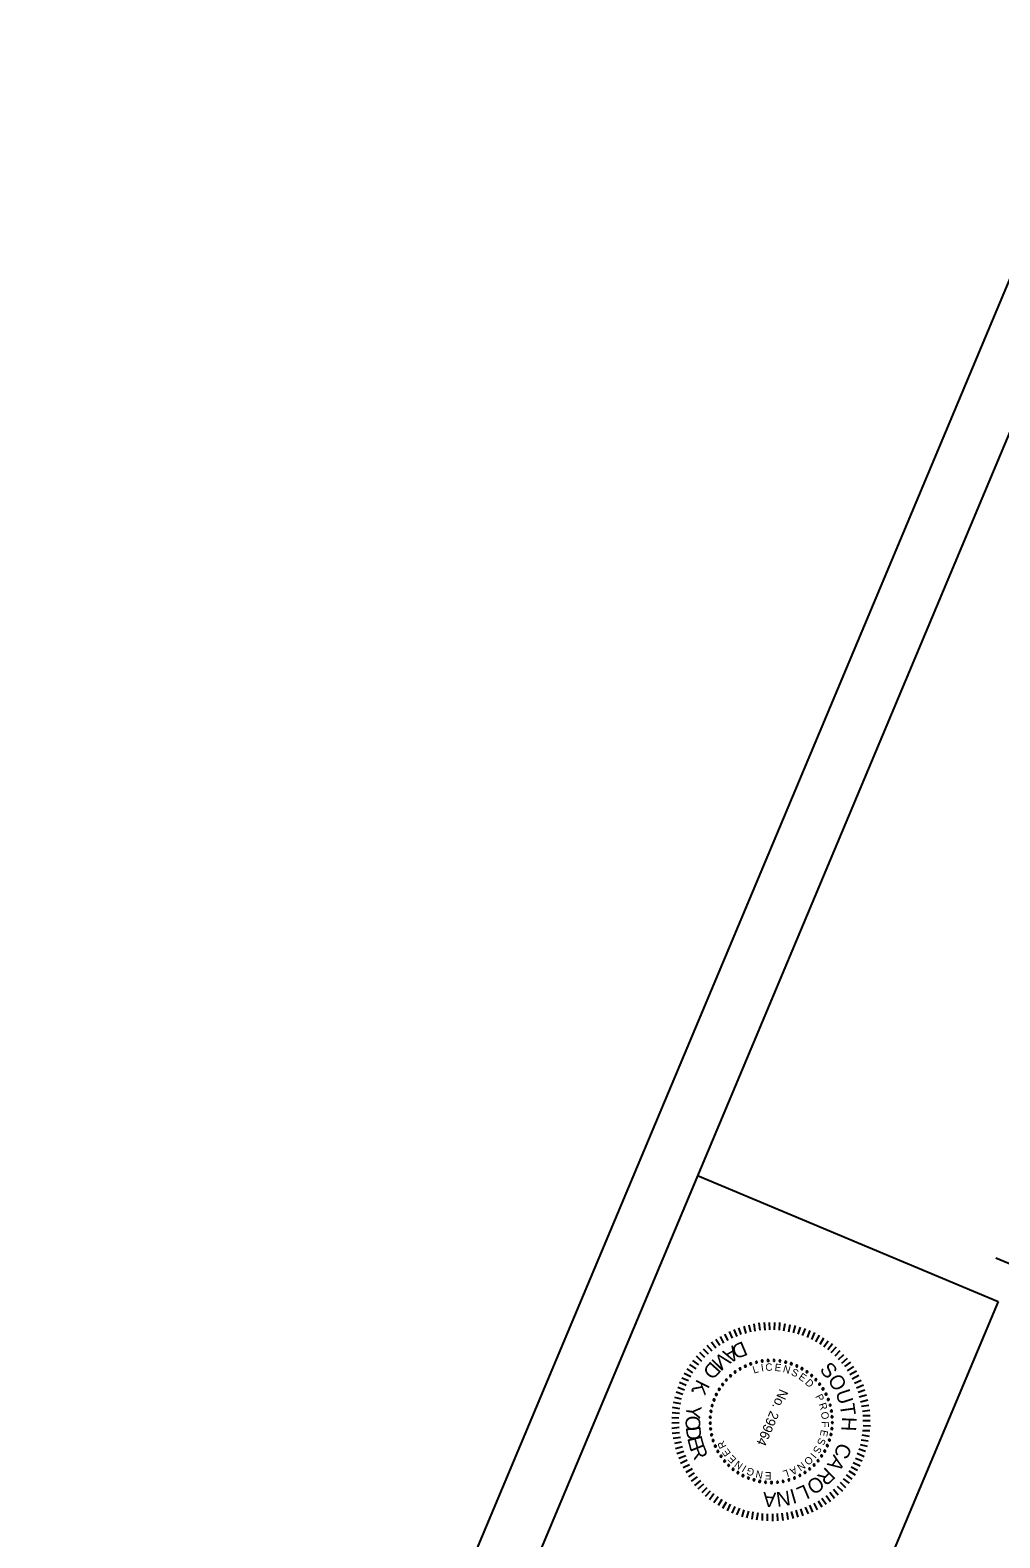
# Model space of a CAD drawing. Extents: x 1968564 to 1968701, y 796599 to 796766.
# Drawn here: x 1968563.8 to 1968596.6, y 796669.3 to 796720.2 of the extents above; entities that cross this region are included whole.
import ezdxf

# ---------------------------------------------------------------- set-up
doc = ezdxf.new("R2010")
doc.units = 0
for name, color, linetype in [('BR_AUTO DIMENSION', 7, 'Continuous'), ('BR_BORDER LINES', 7, 'Continuous'), ('BR_TEXT', 7, 'Continuous'), ('Level 31', 7, 'Continuous')]:
    doc.layers.add(name, color=color, linetype=linetype)

msp = doc.modelspace()

# ---------------------------------------------------------------- linework, layer by layer
at = {"layer": 'BR_AUTO DIMENSION'}
msp.add_line((1968596.437, 796678.704), (1968603.817, 796675.609), dxfattribs=at)
at = {"layer": 'BR_BORDER LINES'}
for p, q in [((1968618.549, 796758.212), (1968566.464, 796634.028)), ((1968586.369, 796681.485), (1968596.513, 796677.23)), ((1968596.513, 796677.23), (1968588.212, 796657.44))]:
    msp.add_line(p, q, dxfattribs=at)
at = {"layer": 'BR_TEXT'}
for p, q in [((1968587.703, 796676.052), (1968587.606, 796676.288)), ((1968587.843, 796676.119), (1968587.761, 796676.345)), ((1968588.006, 796676.158), (1968587.939, 796676.403)), ((1968588.169, 796676.199), (1968588.112, 796676.441)), ((1968588.31, 796676.232), (1968588.279, 796676.481)), ((1968588.484, 796676.263), (1968588.452, 796676.511)), ((1968588.647, 796676.267), (1968588.626, 796676.523)), ((1968588.806, 796676.274), (1968588.796, 796676.528)), ((1968588.969, 796676.278), (1968588.982, 796676.527)), ((1968589.13, 796676.262), (1968589.148, 796676.523)), ((1968589.284, 796676.248), (1968589.327, 796676.495)), ((1968589.45, 796676.207), (1968589.498, 796676.458)), ((1968589.611, 796676.182), (1968589.673, 796676.421)), ((1968589.769, 796676.133), (1968589.838, 796676.372)), ((1968589.915, 796676.081), (1968590.011, 796676.321)), ((1968590.076, 796676.02), (1968590.175, 796676.25)), ((1968586.861, 796675.562), (1968586.698, 796675.748)), ((1968586.988, 796675.657), (1968586.838, 796675.856)), ((1968587.125, 796675.751), (1968586.982, 796675.947)), ((1968587.253, 796675.831), (1968587.138, 796676.052)), ((1968587.4, 796675.913), (1968587.29, 796676.136)), ((1968587.546, 796675.993), (1968587.442, 796676.22)), ((1968590.224, 796675.949), (1968590.326, 796676.185)), ((1968590.366, 796675.877), (1968590.488, 796676.093)), ((1968590.51, 796675.796), (1968590.635, 796676.008)), ((1968590.626, 796675.702), (1968590.782, 796675.907)), ((1968590.77, 796675.61), (1968590.92, 796675.811)), ((1968586.408, 796675.099), (1968586.212, 796675.243)), ((1968586.509, 796675.212), (1968586.33, 796675.386)), ((1968586.616, 796675.339), (1968586.441, 796675.507)), ((1968586.74, 796675.453), (1968586.572, 796675.63)), ((1968590.884, 796675.509), (1968591.063, 796675.701)), ((1968591.013, 796675.401), (1968591.184, 796675.582)), ((1968591.128, 796675.277), (1968591.31, 796675.449)), ((1968591.236, 796675.156), (1968591.427, 796675.321)), ((1968586.137, 796674.692), (1968585.916, 796674.806)), ((1968586.215, 796674.831), (1968586.015, 796674.957)), ((1968586.318, 796674.958), (1968586.114, 796675.109)), ((1968591.335, 796675.039), (1968591.537, 796675.187)), ((1968591.433, 796674.892), (1968591.638, 796675.039)), ((1968591.507, 796674.767), (1968591.73, 796674.888)), ((1968591.589, 796674.62), (1968591.809, 796674.742)), ((1968585.932, 796674.242), (1968585.702, 796674.333)), ((1968585.989, 796674.401), (1968585.765, 796674.497)), ((1968586.065, 796674.551), (1968585.838, 796674.649)), ((1968591.666, 796674.478), (1968591.89, 796674.573)), ((1968591.734, 796674.322), (1968591.965, 796674.417)), ((1968591.789, 796674.172), (1968592.019, 796674.256)), ((1968585.81, 796673.775), (1968585.561, 796673.822)), ((1968585.833, 796673.941), (1968585.602, 796673.995)), ((1968585.878, 796674.09), (1968585.644, 796674.172)), ((1968591.829, 796674.012), (1968592.076, 796674.082)), ((1968591.871, 796673.849), (1968592.119, 796673.914)), ((1968591.901, 796673.701), (1968592.148, 796673.73)), ((1968585.738, 796673.294), (1968585.496, 796673.305)), ((1968585.757, 796673.458), (1968585.508, 796673.472)), ((1968585.771, 796673.613), (1968585.529, 796673.65)), ((1968591.934, 796673.534), (1968592.181, 796673.562)), ((1968591.946, 796673.38), (1968592.193, 796673.39)), ((1968591.951, 796673.217), (1968592.194, 796673.217)), ((1968585.745, 796673.135), (1968585.496, 796673.122)), ((1968585.751, 796672.975), (1968585.497, 796672.95)), ((1968585.764, 796672.805), (1968585.515, 796672.774)), ((1968591.919, 796672.734), (1968592.164, 796672.688)), ((1968591.938, 796672.882), (1968592.184, 796672.874)), ((1968591.953, 796673.048), (1968592.201, 796673.035)), ((1968585.793, 796672.647), (1968585.548, 796672.607)), ((1968585.819, 796672.49), (1968585.586, 796672.434)), ((1968585.862, 796672.33), (1968585.625, 796672.256)), ((1968585.907, 796672.172), (1968585.669, 796672.088)), ((1968591.811, 796672.257), (1968592.042, 796672.177)), ((1968591.858, 796672.409), (1968592.097, 796672.347)), ((1968591.892, 796672.566), (1968592.132, 796672.526)), ((1968585.973, 796672.021), (1968585.738, 796671.935)), ((1968586.023, 796671.876), (1968585.797, 796671.768)), ((1968586.102, 796671.723), (1968585.884, 796671.615)), ((1968591.553, 796671.655), (1968591.77, 796671.543)), ((1968591.626, 796671.799), (1968591.86, 796671.691)), ((1968591.702, 796671.949), (1968591.929, 796671.852)), ((1968591.759, 796672.108), (1968591.995, 796672.006)), ((1968586.187, 796671.581), (1968585.975, 796671.46)), ((1968586.259, 796671.453), (1968586.06, 796671.311)), ((1968586.36, 796671.313), (1968586.159, 796671.168)), ((1968586.467, 796671.189), (1968586.266, 796671.025)), ((1968591.281, 796671.248), (1968591.481, 796671.095)), ((1968591.384, 796671.383), (1968591.58, 796671.239)), ((1968591.476, 796671.519), (1968591.684, 796671.385)), ((1968586.571, 796671.066), (1968586.381, 796670.901)), ((1968586.68, 796670.944), (1968586.511, 796670.77)), ((1968586.8, 796670.833), (1968586.63, 796670.655)), ((1968586.919, 796670.737), (1968586.771, 796670.539)), ((1968587.06, 796670.639), (1968586.915, 796670.44)), ((1968590.71, 796670.683), (1968590.859, 796670.481)), ((1968590.836, 796670.793), (1968590.992, 796670.592)), ((1968590.956, 796670.898), (1968591.117, 796670.71)), ((1968591.076, 796671.004), (1968591.256, 796670.833)), ((1968591.185, 796671.129), (1968591.363, 796670.959)), ((1968587.192, 796670.545), (1968587.064, 796670.342)), ((1968587.333, 796670.455), (1968587.208, 796670.243)), ((1968587.472, 796670.388), (1968587.371, 796670.17)), ((1968587.626, 796670.311), (1968587.529, 796670.087)), ((1968587.781, 796670.255), (1968587.686, 796670.034)), ((1968587.929, 796670.199), (1968587.858, 796669.964)), ((1968588.091, 796670.159), (1968588.026, 796669.93)), ((1968588.237, 796670.134), (1968588.199, 796669.889)), ((1968589.525, 796670.149), (1968589.593, 796669.907)), ((1968589.686, 796670.185), (1968589.755, 796669.953)), ((1968589.846, 796670.236), (1968589.926, 796669.996)), ((1968590.004, 796670.291), (1968590.097, 796670.064)), ((1968590.15, 796670.352), (1968590.246, 796670.124)), ((1968590.291, 796670.429), (1968590.411, 796670.202)), ((1968590.437, 796670.508), (1968590.566, 796670.296)), ((1968590.569, 796670.598), (1968590.715, 796670.389)), ((1968588.405, 796670.099), (1968588.364, 796669.855)), ((1968588.554, 796670.08), (1968588.545, 796669.834)), ((1968588.724, 796670.067), (1968588.713, 796669.825)), ((1968588.893, 796670.069), (1968588.895, 796669.822)), ((1968589.057, 796670.077), (1968589.067, 796669.823)), ((1968589.211, 796670.089), (1968589.244, 796669.844)), ((1968589.382, 796670.113), (1968589.42, 796669.869))]:
    msp.add_line(p, q, dxfattribs=at)
for centre, start, end in [((1968588.355, 796675.186), 14.1575, 194.1575), ((1968588.55, 796675.225), 8.619, 188.619), ((1968588.55, 796675.225), 188.619, 8.619), ((1968588.749, 796675.244), 3.0805, 183.0805), ((1968588.749, 796675.244), 183.0805, 3.0805), ((1968588.948, 796675.245), 357.5421, 177.5421), ((1968588.948, 796675.245), 177.5421, 357.5421), ((1968589.147, 796675.227), 352.0036, 172.0036), ((1968589.147, 796675.227), 172.0036, 352.0036), ((1968589.342, 796675.189), 346.4652, 166.4652), ((1968587.482, 796674.724), 41.8498, 221.8498), ((1968587.482, 796674.724), 221.8498, 41.8498), ((1968587.637, 796674.849), 36.3113, 216.3113), ((1968587.637, 796674.849), 216.3113, 36.3113), ((1968587.804, 796674.959), 30.7728, 210.7728), ((1968587.804, 796674.959), 210.7728, 30.7728), ((1968587.98, 796675.052), 25.2344, 205.2344), ((1968587.98, 796675.052), 205.2344, 25.2344), ((1968588.164, 796675.128), 19.6959, 199.6959), ((1968588.164, 796675.128), 199.6959, 19.6959), ((1968588.355, 796675.186), 194.1575, 14.1575), ((1968589.342, 796675.189), 166.4652, 346.4652), ((1968589.533, 796675.133), 160.9267, 340.9267), ((1968589.533, 796675.133), 340.9267, 160.9267), ((1968589.718, 796675.058), 155.3882, 335.3882), ((1968589.718, 796675.058), 335.3882, 155.3882), ((1968589.895, 796674.966), 149.8498, 329.8498), ((1968589.895, 796674.966), 329.8498, 149.8498), ((1968590.062, 796674.857), 144.3113, 324.3113), ((1968590.062, 796674.857), 324.3113, 144.3113), ((1968590.218, 796674.733), 138.7728, 318.7728), ((1968590.218, 796674.733), 318.7728, 138.7728), ((1968587.1, 796674.267), 58.4652, 238.4652), ((1968587.1, 796674.267), 238.4652, 58.4652), ((1968587.212, 796674.431), 52.9267, 232.9267), ((1968587.212, 796674.431), 232.9267, 52.9267), ((1968587.34, 796674.584), 47.3882, 227.3882), ((1968587.34, 796674.584), 227.3882, 47.3882), ((1968590.361, 796674.594), 133.2344, 313.2344), ((1968590.361, 796674.594), 313.2344, 133.2344), ((1968590.49, 796674.443), 127.6959, 307.6959), ((1968590.49, 796674.443), 307.6959, 127.6959), ((1968590.604, 796674.279), 122.1575, 302.1575), ((1968590.604, 796674.279), 302.1575, 122.1575), ((1968586.863, 796673.719), 75.0805, 255.0805), ((1968586.863, 796673.719), 255.0805, 75.0805), ((1968586.924, 796673.909), 69.5421, 249.5421), ((1968586.924, 796673.909), 249.5421, 69.5421), ((1968587.003, 796674.092), 64.0036, 244.0036), ((1968587.003, 796674.092), 244.0036, 64.0036), ((1968590.702, 796674.105), 116.619, 296.619), ((1968590.702, 796674.105), 296.619, 116.619), ((1968590.782, 796673.923), 111.0805, 291.0805), ((1968590.782, 796673.923), 291.0805, 111.0805), ((1968590.844, 796673.733), 105.5421, 285.5421), ((1968590.844, 796673.733), 285.5421, 105.5421), ((1968586.798, 796673.327), 86.1575, 266.1575), ((1968586.821, 796673.525), 80.619, 260.619), ((1968586.798, 796673.327), 266.1575, 86.1575), ((1968586.821, 796673.525), 260.619, 80.619), ((1968590.888, 796673.539), 100.0036, 280.0036), ((1968590.888, 796673.539), 280.0036, 100.0036), ((1968590.912, 796673.341), 94.4652, 274.4652), ((1968590.918, 796673.142), 88.9267, 268.9267), ((1968590.912, 796673.341), 274.4652, 94.4652), ((1968590.918, 796673.142), 268.9267, 88.9267), ((1968586.794, 796673.127), 91.6959, 271.6959), ((1968586.809, 796672.929), 97.2344, 277.2344), ((1968586.794, 796673.127), 271.6959, 91.6959), ((1968586.809, 796672.929), 277.2344, 97.2344), ((1968586.843, 796672.732), 102.7728, 282.7728), ((1968586.843, 796672.732), 282.7728, 102.7728), ((1968590.871, 796672.746), 77.8498, 257.8498), ((1968590.871, 796672.746), 257.8498, 77.8498), ((1968590.904, 796672.943), 83.3882, 263.3882), ((1968590.904, 796672.943), 263.3882, 83.3882), ((1968586.896, 796672.54), 108.3113, 288.3113), ((1968586.896, 796672.54), 288.3113, 108.3113), ((1968586.967, 796672.354), 113.8498, 293.8498), ((1968586.967, 796672.354), 293.8498, 113.8498), ((1968587.056, 796672.176), 119.3882, 299.3882), ((1968587.056, 796672.176), 299.3882, 119.3882), ((1968590.662, 796672.188), 61.2344, 241.2344), ((1968590.662, 796672.188), 241.2344, 61.2344), ((1968590.75, 796672.367), 66.7728, 246.7728), ((1968590.75, 796672.367), 246.7728, 66.7728), ((1968590.82, 796672.554), 72.3113, 252.3113), ((1968590.82, 796672.554), 252.3113, 72.3113), ((1968587.162, 796672.007), 124.9267, 304.9267), ((1968587.162, 796672.007), 304.9267, 124.9267), ((1968587.283, 796671.849), 130.4652, 310.4652), ((1968587.283, 796671.849), 310.4652, 130.4652), ((1968587.42, 796671.703), 136.0036, 316.0036), ((1968587.42, 796671.703), 316.0036, 136.0036), ((1968590.302, 796671.713), 44.619, 224.619), ((1968590.302, 796671.713), 224.619, 44.619), ((1968590.437, 796671.86), 50.1575, 230.1575), ((1968590.437, 796671.86), 230.1575, 50.1575), ((1968590.557, 796672.019), 55.6959, 235.6959), ((1968590.557, 796672.019), 235.6959, 55.6959), ((1968587.569, 796671.572), 141.5421, 321.5421), ((1968587.569, 796671.572), 321.5421, 141.5421), ((1968587.731, 796671.455), 147.0805, 327.0805), ((1968587.731, 796671.455), 327.0805, 147.0805), ((1968587.903, 796671.355), 152.619, 332.619), ((1968587.903, 796671.355), 332.619, 152.619), ((1968588.084, 796671.271), 158.1575, 338.1575), ((1968588.084, 796671.271), 338.1575, 158.1575), ((1968588.273, 796671.206), 163.6959, 343.6959), ((1968588.273, 796671.206), 343.6959, 163.6959), ((1968588.466, 796671.159), 169.2344, 349.2344), ((1968588.466, 796671.159), 349.2344, 169.2344), ((1968588.664, 796671.131), 174.7728, 354.7728), ((1968588.664, 796671.131), 354.7728, 174.7728), ((1968588.863, 796671.122), 0.3113, 180.3113), ((1968589.062, 796671.132), 5.8498, 185.8498), ((1968589.062, 796671.132), 185.8498, 5.8498), ((1968589.259, 796671.161), 11.3882, 191.3882), ((1968589.259, 796671.161), 191.3882, 11.3882), ((1968589.452, 796671.21), 16.9267, 196.9267), ((1968589.452, 796671.21), 196.9267, 16.9267), ((1968589.64, 796671.277), 22.4652, 202.4652), ((1968589.64, 796671.277), 202.4652, 22.4652), ((1968589.82, 796671.361), 28.0036, 208.0036), ((1968589.82, 796671.361), 208.0036, 28.0036), ((1968589.992, 796671.463), 33.5421, 213.5421), ((1968589.992, 796671.463), 213.5421, 33.5421), ((1968590.153, 796671.581), 39.0805, 219.0805), ((1968590.153, 796671.581), 219.0805, 39.0805), ((1968588.863, 796671.122), 180.3113, 0.3113)]:
    msp.add_arc(centre, 0.028, start, end, dxfattribs=at)
at = {"layer": 'Level 31'}
msp.add_lwpolyline([(1968619.541, 796765.748), (1968563.846, 796632.955), (1968644.997, 796598.919), (1968700.693, 796731.712)], close=True, dxfattribs=at)

# ---------------------------------------------------------------- texts
at = {"layer": 'BR_TEXT'}
for s, height, rotation, p in [('A', 0.494, 210.0837, (1968587.565, 796675.761)), ('D', 0.494, 202.6513, (1968587.91, 796675.906)), ('I', 0.494, 225.4441, (1968586.926, 796675.33)), ('V', 0.494, 217.7639, (1968587.231, 796675.567)), ('D', 0.494, 228.0455, (1968586.83, 796675.24)), ('L', 0.249, 17.2055, (1968588.272, 796674.797)), ('I', 0.249, 8.3471, (1968588.527, 796674.867)), ('C', 0.249, 3.6726, (1968588.665, 796674.887)), ('E', 0.249, 353.7815, (1968588.961, 796674.893)), ('N', 0.249, 344.5792, (1968589.232, 796674.853)), ('S', 0.249, 335.032, (1968589.504, 796674.765)), ('E', 0.249, 325.4848, (1968589.757, 796674.634)), ('S', 0.496, 310.4972, (1968590.466, 796674.923)), ('O', 0.496, 299.2727, (1968590.748, 796674.608)), ('.', 0.494, 250.4048, (1968586.196, 796674.318)), ('K', 0.494, 243.344, (1968586.357, 796674.635)), ('No. 29964', 0.327, 246.7728, (1968589.144, 796674.304)), ('D', 0.249, 316.2825, (1968589.977, 796674.47)), ('U', 0.496, 288.0483, (1968591.016, 796674.172)), ('P', 0.249, 297.1881, (1968590.336, 796674.029)), ('R', 0.249, 287.6409, (1968590.455, 796673.771)), ('T', 0.496, 277.7452, (1968591.167, 796673.757)), ('O', 0.494, 269.6673, (1968585.968, 796673.38)), ('Y', 0.494, 262.1109, (1968586.02, 796673.756)), ('O', 0.249, 278.0937, (1968590.53, 796673.496)), ('H', 0.496, 267.6097, (1968591.243, 796673.344)), ('D', 0.494, 277.3475, (1968585.967, 796672.993)), ('E', 0.494, 284.7799, (1968586.015, 796672.622)), ('E', 0.249, 258.6564, (1968590.538, 796672.918)), ('F', 0.249, 267.8587, (1968590.559, 796673.192)), ('R', 0.494, 291.8408, (1968586.104, 796672.278)), ('R', 0.249, 117.028, (1968587.355, 796672.343)), ('E', 0.249, 126.2304, (1968587.508, 796672.115)), ('S', 0.249, 239.9068, (1968590.363, 796672.388)), ('S', 0.249, 249.454, (1968590.474, 796672.65)), ('C', 0.496, 246.7942, (1968591.142, 796672.5)), ('E', 0.249, 135.4327, (1968587.697, 796671.915)), ('N', 0.249, 144.9799, (1968587.923, 796671.741)), ('I', 0.249, 149.6544, (1968588.044, 796671.671)), ('A', 0.249, 205.903, (1968589.658, 796671.676)), ('N', 0.249, 215.4502, (1968589.897, 796671.831)), ('O', 0.249, 225.6852, (1968590.121, 796672.04)), ('I', 0.249, 230.3596, (1968590.21, 796672.147)), ('A', 0.496, 235.4441, (1968590.972, 796672.087)), ('G', 0.249, 159.5455, (1968588.315, 796671.556)), ('N', 0.249, 169.0926, (1968588.593, 796671.49)), ('E', 0.249, 178.295, (1968588.867, 796671.471)), ('L', 0.249, 196.7006, (1968589.407, 796671.565)), ('O', 0.496, 213.8329, (1968590.43, 796671.38)), ('R', 0.496, 224.6804, (1968590.708, 796671.664)), ('A', 0.496, 176.7252, (1968589.031, 796670.78)), ('N', 0.496, 187.9497, (1968589.466, 796670.854)), ('I', 0.496, 195.9073, (1968589.621, 796670.922)), ('L', 0.496, 203.1948, (1968590.006, 796671.07))]:
    msp.add_text(s, height=height, rotation=rotation, dxfattribs=at).set_placement(p)

doc.saveas('drawing.dxf')
